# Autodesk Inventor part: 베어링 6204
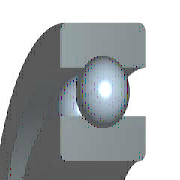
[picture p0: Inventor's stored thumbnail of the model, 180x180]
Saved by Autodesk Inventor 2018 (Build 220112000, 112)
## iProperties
Created: 2012-02
Part Number: 베어링 6204
Material: 강철, 연강
Description: 깊은 그루브 볼 베어링
Document SubType Name: Modeling
Standard: KS B 2023
Designer: mduedu
Standards Organization: KS
Language: ko-KR
Size Designation: 6203 - 17 x 40 x 12
Categories: <MemberInstance><Categories><Category DisplayName="샤프트 부품" InternalName="7f7aeb1f-a693-4053-b835-cee3144e0d98" Mnemonic="SHFT"><Category DisplayName="베어링" Inter
Density: 1 g/cm^3
Appearance: 노란색
IsCustomPart: 1
Author: mduedu
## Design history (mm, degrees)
sketch "스케치" dims "d0" = 7.02 (= -0.26 x WD + 0.26 x BD)
  geometry: L1 (3.49, 16.75)-(10.51, 16.75); L2 (7, 16.75)-(7, 13.24); L3 (7, 16.75)-(7, 20.26); L4 (4.392, 14.401)-(0, 14.401); L5 (0, 10)-(14, 10); L6 (4.392, 19.099)-(0, 19.099); L7 (0, 23.5)-(14, 23.5); L8 (14, 10)-(14, 14.401); L9 (9.608, 14.401)-(14, 14.401); L10 (9.608, 19.099)-(14, 19.099); L11 (14, 23.5)-(14, 19.099); L12 (-2.4, 0)-(14.4, 0) reference; L13 (0, 7.3)-(0, 26.2) reference
  constraints: 22 end point, 4 point on line, 2 collinear, 2 perpendicular, 2 symmetric about line, 1 midpoint, 1 parallel, 14 other
  dimensions: "d9" = 20 diameter of L5 L12 (= WD); "d11" = 47 diameter of L7 L12 (= BD); "d12" = 14 distance between parallel lines of L8 L13 (= KB); "d13" = 28.802 diameter of L9 L12 (= 0.326 x BD + 0.674 x WD)
revolve "본체" stored, may be unused: angle "d6" = 90 deg
revolve "볼" stored, may be unused: angle "d7" = 90 deg
pattern_circular "IDS_ARRAYBALL[SIMPL:T]" dims angle "d3" = 360 deg
body "Solid1"
fillet "모깎기1" dims "d1" = 1 (= KRS)
other parameters: "WD" = 20 [user parameter; used in 5 equation terms], "BD" = 47 [user parameter; used in 5 equation terms], "KB" = 14 [user parameter; used in 1 equation term], "KRS" = 1 [user parameter; used in 1 equation term], "d4" = 0, "d5" = 0, "d8" = 0, "d14" = 0, "d15" = 0, "BBA" = 0 [user parameter], "BC0" = 4750000 [user parameter], "BC" = 9560000 [user parameter], "BR" = 23.5 (= 0.5 x BD) [user parameter]
